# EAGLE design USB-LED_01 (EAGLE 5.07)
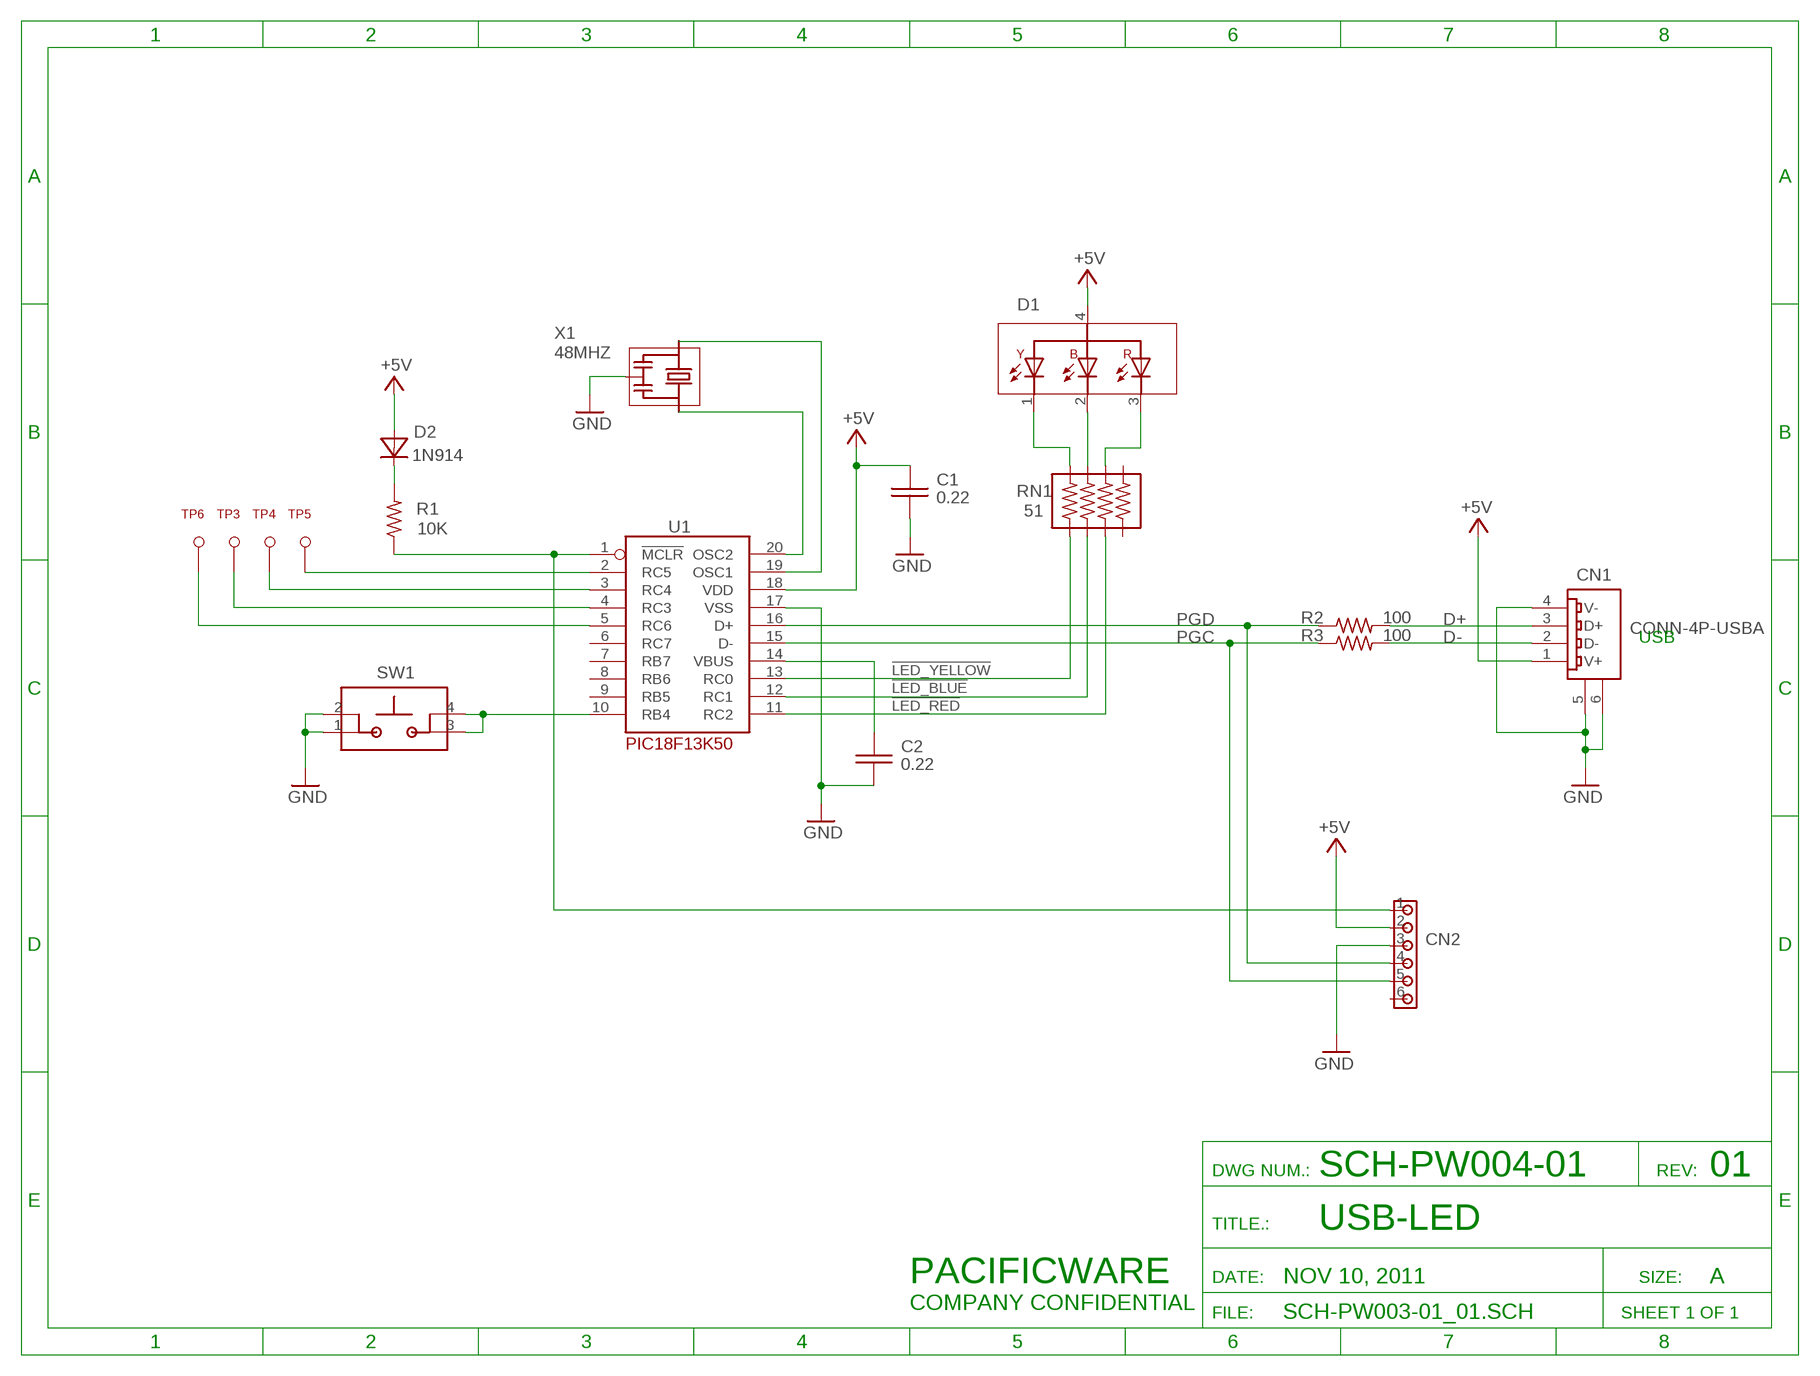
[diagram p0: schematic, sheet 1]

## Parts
C1  0.22  CAP-0603  [C0603]
C2  0.22  CAP-0603  [C0603]
CN1  CONN-4P-USBA  [CONN-4P-USBA]
CN2  CONN-6P-100  [CONN-6P-100]
D1  LED_TRIPLE  [PLCC4]
D2  1N914  DIODE-SOD323  [SOD323F]
R1  10K  RES-0603  [R0603]
R2  100  RES-0603  [R0603]
R3  100  RES-0603  [R0603]
RN1  51  RN-0201MM  [RN-0201MM]
SW1  SWITCH-SPS-4P  [SWITCH-TL3315NF]
TP3  TP_040  [HOLE_040_P]
TP4  TP_040  [HOLE_040_P]
TP5  TP_040  [HOLE_040_P]
TP6  TP_040  [HOLE_040_P]
U1  PIC18F13K50  [QFN20-5X5]
X1  48MHZ  RESONATOR-3PIN  [CSTCW_RESONATOR]

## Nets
!LED_BLUE: RN1.P$2 U1.12(RC1)
!LED_RED: RN1.P$3 U1.11(RC2)
!LED_YELLOW: RN1.P$1 U1.13(RC0)
+5V [power]: C1.1 CN1.1(V+) CN2.2 D1.4 D2.P$1(A) U1.18(VDD)
D+: CN1.3(D+) R2.2
D-: CN1.2(D-) R3.2
GND [power]: C1.2 C2.2 CN1.4(V-) CN1.5 CN1.6 CN2.3 SW1.1 SW1.2 U1.17(VSS) X1.P$2
N$1: TP5.1 U1.2(RC5)
N$2: TP4.1 U1.3(RC4)
N$3: U1.19(OSC1) X1.P$1
N$4: U1.20(OSC2) X1.P$3
N$5: TP3.1 U1.4(RC3)
N$6: C2.1 U1.14(VBUS)
N$7: D2.P$2(C) R1.2
N$8: CN2.1 R1.1 U1.1(!MCLR)
N$9: D1.2 RN1.P$7
N$10: D1.1 RN1.P$8
N$11: D1.3 RN1.P$6
N$12: TP6.1 U1.5(RC6)
N$13: SW1.3 SW1.4 U1.10(RB4)
PGC: CN2.5 R3.1 U1.15(D-)
PGD: CN2.4 R2.1 U1.16(D+)
Unconnected: CN2.6 RN1.P$4 RN1.P$5 U1.6(RC7) U1.7(RB7) U1.8(RB6) U1.9(RB5)

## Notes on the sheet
- USB
- DWG NUM.: | SCH-PW004-01 | REV: | 01
- TITLE.: | USB-LED
- PACIFICWARE | DATE: | NOV 10, 2011 | SIZE: | A
- COMPANY CONFIDENTIAL
- FILE: | SCH-PW003-01_01.SCH | SHEET 1 OF 1

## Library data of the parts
C1 C2 = Pacificware:CAP-0603
CN1 = Pacificware:CONN-4P-USBA: Molex SD-48037-002
CN2 = Pacificware:CONN-6P-100
D1 = Pacificware:LED_TRIPLE: Bivar SMP4
D2 = Pacificware:DIODE-SOD323
R1-R3 = Pacificware:RES-0603
RN1 = Pacificware:RN-0201MM
SW1 = Pacificware:SWITCH-SPS-4P: E-Switch TL3315 Series
TP3-TP6 = Pacificware:TP_040
U1 = Pacificware:PIC18F13K50
X1 = Pacificware:RESONATOR-3PIN: Murata CSTCW series

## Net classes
0 default: width 0.203 mm, clearance 0.203 mm
1 power: width 0.381 mm, clearance 0.203 mm to class 0, clearance 0.203 mm

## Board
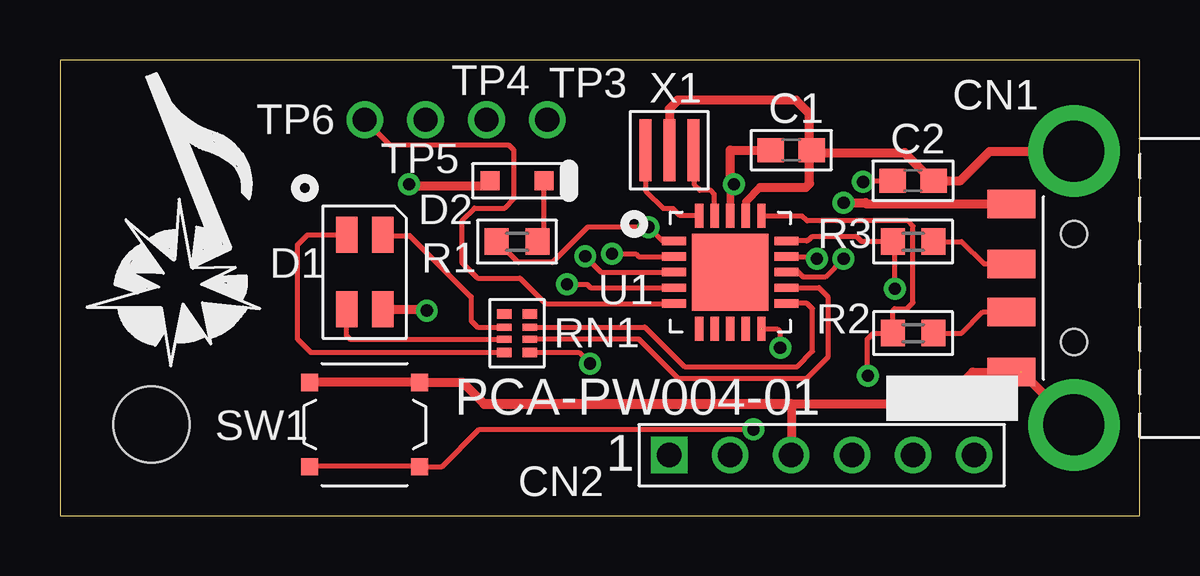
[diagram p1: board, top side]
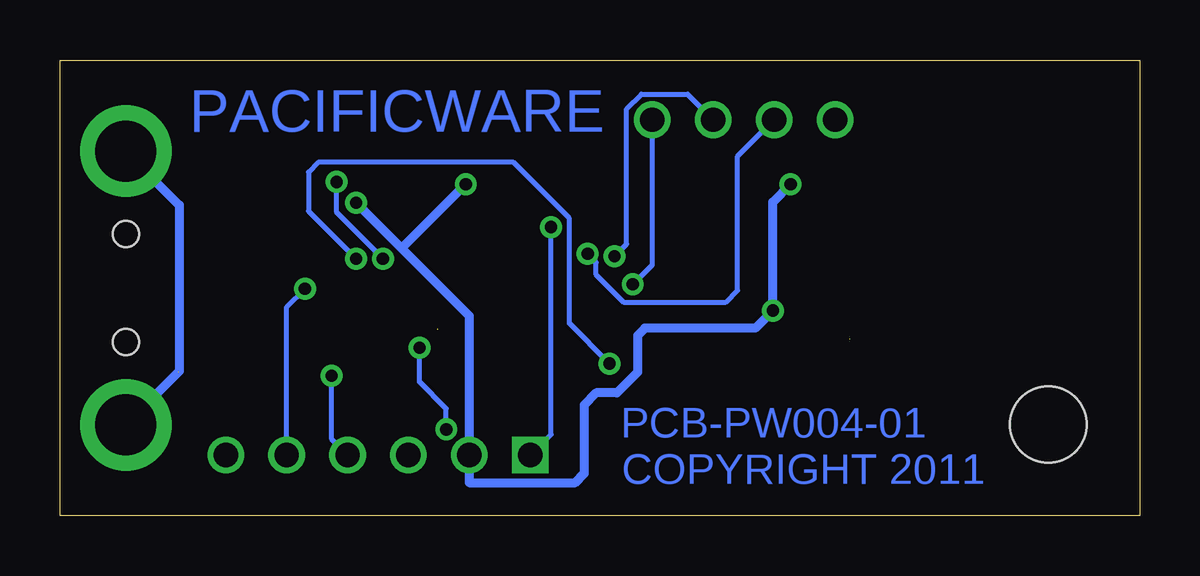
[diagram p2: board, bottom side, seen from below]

Size 45.01 x 19 mm. Coordinates in mm from the lower left corner, seen from the top.
Outline: 0,0 45.01,0 45.01,19 0,19 0,0
Copper layers (1*16): Top 0.0178mm / dielectric 1.4986mm / Bottom 0.0178mm
Design rules "SSC-EAGLE-2Lyr_v1.0.0.3": minimum track width 6mil, minimum drill 14mil, track to track 6mil, track to pad 6mil, pad to pad 6mil, via to via 6mil, smd to smd 6mil, copper to edge 20mil, drill to drill 16mil, minimum pad ring 8mil, minimum via ring 8mil, stop-mask expansion 3mil, vias tented up to drill 0mil, thermal gap 10mil

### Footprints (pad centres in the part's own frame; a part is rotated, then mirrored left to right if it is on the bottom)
C0603 = smd 1.1 x 1: 1 -0.85,0; 2 0.85,0
CONN-4P-USBA = smd 1.2 x 2: 1 3.5,2.6; 2 1,2.6; 3 -1,2.6; 4 -3.5,2.6 | drill 2.54 round: 5 5.7,0; 6 -5.7,0 | hole 1.092: 2.25,0; -2.25,0
CONN-6P-100 = drill 1.016 square: 1 0,0 | drill 1.016 round: 2 2.54,0; 3 5.08,0; 4 7.62,0; 5 10.16,0; 6 12.7,0
PLCC4 = smd 0.9 x 1.5: 1 -0.75,1.55; 2 -0.75,-1.55; 3 0.75,1.55; 4 0.75,-1.55
SOD323F = smd 0.8 x 0.8: P$1 1.125,0; P$2 -1.125,0
R0603 = smd 1 x 1.1: 1 -0.85,0; 2 0.85,0
RN-0201MM = smd 0.4 x 0.6: P$1 -0.8,-0.525; P$4 0.8,-0.525; P$5 0.8,0.525; P$8 -0.8,0.525 | smd 0.3 x 0.6: P$2 -0.25,-0.525; P$3 0.25,-0.525; P$6 0.25,0.525; P$7 -0.25,0.525
SWITCH-TL3315NF = smd 0.711 x 0.711: 1 -2.286,1.753; 2 2.286,1.753; 3 -2.286,-1.753; 4 2.286,-1.753
HOLE_040_P = drill 1.016 round: 1 0,0
QFN20-5X5 = smd 0.35 x 1: 1 -1.3,-2.35; 2 -0.65,-2.35; 3 0,-2.35; 4 0.65,-2.35; 5 1.3,-2.35; 11 1.3,2.35; 12 0.65,2.35; 13 0,2.35; 14 -0.65,2.35; 15 -1.3,2.35 | smd 1 x 0.35: 6 2.35,-1.3; 7 2.35,-0.65; 8 2.35,0; 9 2.35,0.65; 10 2.35,1.3; 16 -2.35,1.3; 17 -2.35,0.65; 18 -2.35,0; 19 -2.35,-0.65; 20 -2.35,-1.3 | smd 3.2 x 3.2: P$21 0,0
HOLE_125NP = hole 3.175: 0,0
CSTCW_RESONATOR = smd 0.5 x 2.6: P$1 -1,0; P$2 0,0; P$3 1,0

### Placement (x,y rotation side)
C1  30.48,15.24 0 top
C2  35.56,13.97 0 top
CN1  42.27,9.5 90 top
CN2  25.4,2.54 0 top
D1  12.7,10.16 0 top
D2  19.05,13.97 180 top
R1  19.05,11.43 0 top
R2  35.56,7.62 0 top
R3  35.56,11.43 0 top
RN1  19.05,7.62 90 top
SW1  12.7,3.81 0 top
TP3  20.32,16.51 0 top
TP4  17.78,16.51 0 top
TP5  15.24,16.51 0 top
TP6  12.7,16.51 0 top
U1  27.94,10.16 270 top
U$1  [NOTE-SM]  5.08,10.16 0 top
U$2  [HOLE_125NP]  3.81,3.81 0 top
X1  25.4,15.24 180 top

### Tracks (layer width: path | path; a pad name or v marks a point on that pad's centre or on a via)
!LED_BLUE
  Top 0.203: U1.12 31.64,9.51 32,9.14 32,6.6 31.11,5.71 25.78,5.71 24.13,7.37 RN1.P$2
!LED_RED
  Top 0.203: RN1.P$3 24.38,7.87 26.04,6.22 30.73,6.22 31.37,6.86 31.37,8.64 31.14,8.86 U1.11
!LED_YELLOW  (via drill 0.51)
  Top 0.203: v32.66,10.72 31.9,9.96 30.99,9.96 30.79,10.16 U1.13 | RN1.P$1 21.63,6.82 v22.1,6.35
  Bottom 0.203: v22.1,6.35 23.77,8.03 23.77,12.39 26.11,14.73 34.24,14.73 34.65,14.33 34.65,12.7 v32.66,10.72
+5V  (via drill 0.51)
  Top 0.305: 27.94,13.82 U1.18
  Top 0.381: D2.P$1 17.88,13.97 17.68,13.77 14.61,13.77 v14.55,13.82 | C1.1 27.94,15.24 27.94,13.82 v28.09,13.82 | v32.66,13.06 33.58,13.06 33.63,13 CN1.1 | D1.4 15.24,8.61 v15.29,8.56
  Bottom 0.381: 30.76,11.15 27.94,8.33 CN2.2 27.94,1.4 27.91,1.37 23.57,1.37 23.16,1.78 23.16,4.62 22.66,5.13 21.79,5.13 20.93,5.99 20.93,7.52 20.62,7.82 16.03,7.82 v15.29,8.56 | 30.76,11.15 v32.66,13.06 | 30.76,11.15 v28.09,13.82 | 14.53,13.79 v14.55,13.82 15.29,13.08 v15.29,8.56 | v15.29,8.56 15.37,8.48
D+
  Top 0.203: 36.42,7.62 R2.2 37.59,7.62 38.47,8.5 CN1.3
D-
  Top 0.203: 36.42,11.43 R3.2 37.59,11.43 38.52,10.5 CN1.2
GND  (1 unrouted)
  Top 0.305: U1.17 28.59,13.1 29.18,13.69
  Top 0.381: X1.P$2 25.4,16.97 25.76,17.32 30.68,17.32 31.24,16.76 31.24,15.33 C1.2 | SW1.1 10.41,5.59 14.99,5.59 SW1.2 16.79,5.56 17.68,4.67 | CN2.3 30.48,4.67 36.73,4.67 38.05,5.99 40.07,5.99 | 29.18,13.69 31.09,13.69 31.24,13.84 31.24,15.15 C1.2 | C1.2 31.43,15.14 35.2,15.14 36.37,13.97 C2.2 37.54,13.97 38.76,15.19 42.26,15.19 CN1.5 | CN1.4 40.07,6 CN1.6
  Top 0.406: 17.68,4.67 30.48,4.67 | SW1.2 15.01,5.59
  Bottom 0.381: CN1.5 40.03,12.95 40.03,6.04 CN1.6
N$1  (via drill 0.51)
  Top 0.203: v23.01,10.92 24,10.92 24.11,10.81 U1.2
  Bottom 0.203: v23.01,10.92 22.66,10.57 22.66,10.06 21.49,8.89 17.27,8.89 16.76,9.4 16.76,14.99 TP5.1 15.44,16.31
N$2  (via drill 0.51)
  Top 0.203: v21.89,10.82 22.55,10.16 U1.3
  Bottom 0.203: v21.89,10.82 21.39,11.33 21.39,16.97 20.78,17.58 18.85,17.58 TP4.1
N$3
  Top 0.203: X1.P$1 26.45,15.19 26.45,13.78 26.67,13.56 27.13,13.56 27.28,13.41 U1.19
N$4
  Top 0.203: X1.P$3 24.43,15.21 24.43,13.51 25.15,12.8 25.55,12.8 25.84,12.51 U1.20
N$5  (via drill 0.51)
  Top 0.203: v21.13,9.65 21.97,9.65 22.11,9.51 U1.4
  Bottom 0.203: v21.13,9.65 20.32,10.46 TP3.1
N$6  (via drill 0.51)
  Top 0.203: 30.38,10.72 30.33,10.77 U1.14 31.46,10.81 v31.55,10.72 | v33.48,13.92 33.53,13.97 C2.1
  Bottom 0.203: v31.55,10.72 33.48,12.65 v33.48,13.92
N$7
  Top 0.203: D2.P$2 20.17,13.97 20.17,11.43 R1.2
N$8  (via drill 0.51)
  Top 0.203: R1.1 18.24,11.43 19.1,10.57 20.52,10.57 22,12.04 v24.54,12.04 25.12,11.46 U1.1
  Bottom 0.203: CN2.1 24.54,3.4 v24.54,12.04
N$9  (1 unrouted)
  Top 0.203: 12.09,7.37 RN1.P$7 | 12.09,7.37 11.94,7.52 11.94,8.6 D1.2
N$10
  Top 0.203: D1.1 10.31,11.71 9.91,11.3 9.91,7.37 10.45,6.82 RN1.P$8
N$11
  Top 0.203: 13.48,11.68 14.58,11.68 17.12,9.14 17.14,9.14 17.14,8.13 17.4,7.87 RN1.P$6 | D1.3 13.48,11.68 | 13.48,11.68 13.46,11.68
N$12
  Top 0.203: TP6.1 13.77,15.44 18.72,15.44 18.92,15.24 18.92,13.21 18.54,12.83 17.27,12.83 16.76,12.32 16.76,10.54 17.4,9.91 19.18,9.91 20.24,8.84 25.57,8.84 U1.5
N$13  (via drill 0.51)  (1 unrouted)
  Top 0.203: SW1.3 10.41,2.08 14.99,2.08 SW1.4 15.93,2.06 17.48,3.61 v28.91,3.61 | 29.26,7.77 29.92,7.77 30.02,7.67 v30.02,7.01
  Bottom 0.203: v28.91,3.61 28.91,4.47 30.02,5.59 v30.02,7.01
PGC  (via drill 0.51)
  Top 0.203: 34.65,11.48 34.7,11.43 R3.1 | v34.8,9.47 34.8,11.38 34.75,11.43 R3.1 | R3.1 34.68,11.46 | U1.15 31.12,11.46 31.14,11.48 31.19,11.48 31.34,11.63 33.22,11.63 33.43,11.43 R3.1
  Bottom 0.203: CN2.5 35.56,8.71 v34.8,9.47
PGD  (via drill 0.51)
  Top 0.203: v33.68,5.84 33.66,5.87 33.66,7.37 33.91,7.62 R2.1 34.71,8.55 34.8,8.64 35.31,8.64 35.56,8.89 35.56,12.09 35.36,12.29 31.14,12.29 30.94,12.5 29.25,12.5 U1.16
  Bottom 0.203: CN2.4 33.68,3.2 v33.68,5.84

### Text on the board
Bottom: PACIFICWARE | PCB-PW004-01 | COPYRIGHT 2011
tNames: PCA-PW004-01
